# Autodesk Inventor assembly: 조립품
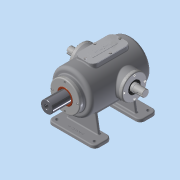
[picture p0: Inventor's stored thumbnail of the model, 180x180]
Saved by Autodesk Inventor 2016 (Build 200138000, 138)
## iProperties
Created: 2018-11
Part Number: 조립품
Material: 일반
Document SubType Name: Assembly
Designer: 공506_39
Author: 공506_39
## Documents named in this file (15)
- C:\Users\공506_39\Desktop\381121V1001\조립품.iam
- C:\Users\공506_39\Desktop\381121V1001\가변스프링.ipt
- C:\Users\공506_39\Desktop\381121V1001\베어링 6205.ipt
- 베어링 6205.ipt
- C:\Users\공506_39\Desktop\381121V1001\본체.ipt
- C:\Users\공506_39\Desktop\381121V1001\볼트 M4x0.7.ipt
- C:\Users\공506_39\Desktop\381121V1001\부시.ipt
- C:\Users\공506_39\Desktop\381121V1001\상부커버.ipt
- C:\Users\공506_39\Desktop\381121V1001\슬라이드 커버.ipt
- C:\Users\공506_39\Desktop\381121V1001\슬라이드.ipt
- C:\Users\공506_39\Desktop\381121V1001\오일실.ipt
- 오일실.ipt
- C:\Users\공506_39\Desktop\381121V1001\육각머리볼트 M4.ipt
- C:\Users\공506_39\Desktop\381121V1001\축 커버.ipt
- C:\Users\공506_39\Desktop\381121V1001\편심축.ipt
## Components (13 placed, 2 different names)
1. 가변스프링:1
2. M4x0.7:2
3. M4x0.7:4
4. M4x0.7:5
5. M4x0.7:6
6. M4x0.7:3
7. M4x0.7:7
8. M4x0.7:8
9. M4x0.7:9
10. M4x0.7:1
11. M4x0.7:10
12. M4x0.7:11
13. M4x0.7:12
